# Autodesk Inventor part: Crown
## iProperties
Shininess: 64.0
Length Units: 11272
Angle Units: 11279
Time Units: 11290
Mass Units: 11283
Length Display Precision: 3
Angle Display Precision: 2
Compacted: True
Part Number: Crown
Document SubType Name: Modeling
Created: 2005-03
Designer: Admin
Manufacturer: Standard
Standards Organization: Custom
Density: 1 g/cm^3
Density: 0.0
Volumn: 0.0
Area: 0.0
PropertySet Name: Model Information
Control State: 0
Master: False
Checked Out: False
Author: Admin
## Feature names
1. ExtrusionBlind1
2. ExtrusionThru1
3. ExtrusionThru2
4. Fillet1
5. Hole1
6. Hole2
7. ExtrusionThru3
8. Fillet2
9. Fillet3
10. Fillet4
11. Fillet5
12. ExtrusionThru4
13. ExtrusionThru5
14. Hole3
15. Hole4
16. Hole5
17. Hole6
18. Hole7
19. Revolution1
20. Mirror1
21. Fillet6
